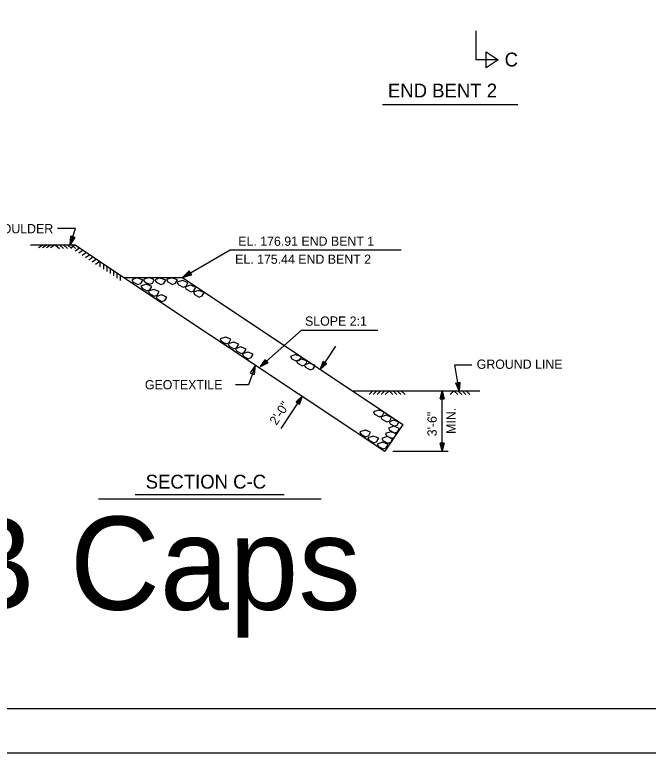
# Model space of a CAD drawing. Extents: x -102 to 265, y 0 to 198.
# Drawn here: x 115.3 to 183.9, y 0 to 80 of the extents above; entities that cross this region are included whole.
import ezdxf

# ---------------------------------------------------------------- set-up
doc = ezdxf.new("R2010")
doc.units = 0
for name, color, linetype in [('Arrowhead Terminators', 7, 'Continuous'), ('Arrowhead Terminators CELL', 7, 'Continuous'), ('Dimension Lines', 7, 'Continuous'), ('Mis Center Lines', 7, 'Continuous'), ('Mis Object Lines', 7, 'Continuous'), ('Miscellaneous Lines', 7, 'Continuous'), ('Plan Sheet', 7, 'Continuous'), ('Plot Shape', 7, 'Continuous'), ('Subtitle Text', 7, 'Continuous'), ('Text', 7, 'Continuous'), ('User Information Notes', 7, 'Continuous')]:
    doc.layers.add(name, color=color, linetype=linetype)

msp = doc.modelspace()

# ---------------------------------------------------------------- linework, layer by layer
at = {"layer": 'Arrowhead Terminators'}
msp.add_lwpolyline([(141.383, 42.059), (140.809, 41.203), (141.279, 41.033)], close=True, dxfattribs=at)
at = {"layer": 'Arrowhead Terminators CELL'}
msp.add_lwpolyline([(167.667, 75.143), (166.377, 74.283), (166.377, 76.002)], close=True, dxfattribs=at)
at = {"layer": 'Dimension Lines'}
for p, q in [((167.667, 75.143), (165.264, 75.143)), ((133.46, 51.561), (138.645, 54.554)), ((138.645, 54.554), (157.172, 54.554)), ((150.054, 44.094), (148.387, 41.594)), ((161.607, 32.712), (161.607, 39.276)), ((146.451, 38.69), (144.123, 35.198)), ((156.255, 32.712), (162.249, 32.712)), ((128.355, 28.052), (144.488, 28.052)), ((124.365, 27.552), (148.478, 27.552))]:
    msp.add_line(p, q, dxfattribs=at)
for points in [[(165.264, 75.143), (165.264, 78.288)], [(121.324, 55.129), (121.875, 56.857), (119.947, 56.857)], [(121.59, 55.965), (121.632, 55.952), (121.324, 55.129), (121.674, 55.939), (121.716, 55.925), (121.324, 55.129), (121.757, 55.911), (121.8, 55.898), (121.324, 55.129), (121.381, 56.031), (121.424, 56.018), (121.324, 55.129), (121.465, 56.005), (121.506, 55.992), (121.324, 55.129), (121.549, 55.978), (121.8, 55.898), (121.381, 56.031), (121.324, 55.129), (121.8, 55.898)], [(134.324, 52.06), (134.349, 52.017), (133.46, 51.561), (134.374, 51.974), (134.399, 51.93), (133.46, 51.561), (134.424, 51.887), (134.449, 51.844), (133.46, 51.561), (134.2, 52.276), (134.224, 52.233), (133.46, 51.561), (134.249, 52.189), (134.274, 52.147), (133.46, 51.561), (134.299, 52.103), (134.449, 51.844), (134.2, 52.276), (133.46, 51.561), (134.449, 51.844)], [(141.916, 41.895), (146.364, 45.837), (154.625, 45.837)], [(142.574, 42.478), (142.603, 42.446), (141.916, 41.895), (142.631, 42.412), (142.661, 42.379), (141.916, 41.895), (142.69, 42.347), (142.719, 42.313), (141.916, 41.895), (142.428, 42.642), (142.457, 42.609), (141.916, 41.895), (142.486, 42.576), (142.515, 42.543), (141.916, 41.895), (142.544, 42.511), (142.719, 42.313), (142.428, 42.642), (141.916, 41.895), (142.719, 42.313)], [(148.874, 42.325), (148.911, 42.301), (148.387, 41.594), (148.948, 42.277), (148.984, 42.252), (148.387, 41.594), (149.02, 42.228), (149.057, 42.203), (148.387, 41.594), (148.692, 42.447), (148.728, 42.423), (148.387, 41.594), (148.765, 42.399), (148.802, 42.374), (148.387, 41.594), (148.838, 42.35), (149.057, 42.203), (148.692, 42.447), (148.387, 41.594), (149.057, 42.203)], [(141.383, 42.059), (140.616, 39.93), (139.212, 39.93)], [(163.418, 39.277), (162.959, 42.076), (164.794, 42.076)], [(163.275, 40.144), (163.319, 40.151), (163.418, 39.277), (163.362, 40.157), (163.406, 40.165), (163.418, 39.277), (163.449, 40.172), (163.492, 40.179), (163.418, 39.277), (163.059, 40.108), (163.103, 40.116), (163.418, 39.277), (163.146, 40.122), (163.189, 40.13), (163.418, 39.277), (163.232, 40.136), (163.492, 40.179), (163.059, 40.108), (163.418, 39.277), (163.492, 40.179)], [(161.607, 38.399), (161.563, 38.399), (161.607, 39.276), (161.519, 38.399), (161.475, 38.399), (161.607, 39.276), (161.431, 38.399), (161.388, 38.399), (161.607, 39.276), (161.826, 38.399), (161.782, 38.399), (161.607, 39.276), (161.738, 38.399), (161.695, 38.399), (161.607, 39.276), (161.65, 38.399), (161.388, 38.399), (161.826, 38.399), (161.607, 39.276), (161.388, 38.399)], [(145.964, 37.96), (145.927, 37.984), (146.451, 38.69), (145.891, 38.009), (145.854, 38.033), (146.451, 38.69), (145.818, 38.057), (145.782, 38.081), (146.451, 38.69), (146.147, 37.838), (146.11, 37.862), (146.451, 38.69), (146.073, 37.887), (146.037, 37.911), (146.451, 38.69), (146.001, 37.935), (145.782, 38.081), (146.147, 37.838), (146.451, 38.69), (145.782, 38.081)], [(161.607, 33.59), (161.65, 33.59), (161.607, 32.712), (161.695, 33.59), (161.738, 33.59), (161.607, 32.712), (161.782, 33.59), (161.826, 33.59), (161.607, 32.712), (161.388, 33.59), (161.431, 33.59), (161.607, 32.712), (161.475, 33.59), (161.519, 33.59), (161.607, 32.712), (161.563, 33.59), (161.826, 33.59), (161.388, 33.59), (161.607, 32.712), (161.826, 33.59)]]:
    msp.add_lwpolyline(points, dxfattribs=at)
at = {"layer": 'Mis Center Lines'}
for points in [[(128.564, 51.499), (128.002, 51.298), (128.122, 51.056), (128.645, 50.776), (128.966, 50.897), (129.167, 51.257), (128.685, 51.459), (128.685, 51.499), (128.564, 51.459)], [(129.816, 51.536), (129.254, 51.336), (129.374, 51.094), (129.896, 50.813), (130.217, 50.934), (130.418, 51.295), (129.937, 51.496), (129.937, 51.536), (129.816, 51.496)], [(131.061, 51.496), (130.499, 51.295), (130.62, 51.054), (131.142, 50.773), (131.463, 50.893), (131.664, 51.255), (131.182, 51.456), (131.182, 51.496), (131.061, 51.456)], [(132.316, 51.521), (131.753, 51.32), (131.874, 51.079), (132.396, 50.799), (132.717, 50.919), (132.918, 51.28), (132.436, 51.481), (132.436, 51.521), (132.316, 51.481)], [(133.46, 51.226), (132.897, 51.025), (133.018, 50.785), (133.541, 50.504), (133.862, 50.624), (134.062, 50.986), (133.581, 51.187), (133.581, 51.226), (133.46, 51.187)], [(129.537, 50.819), (128.975, 50.619), (129.095, 50.378), (129.617, 50.097), (129.938, 50.217), (130.139, 50.579), (129.657, 50.78), (129.657, 50.819), (129.537, 50.78)], [(134.318, 50.714), (133.756, 50.513), (133.876, 50.272), (134.398, 49.991), (134.719, 50.112), (134.92, 50.473), (134.438, 50.674), (134.438, 50.714), (134.318, 50.674)], [(130.329, 50.253), (129.767, 50.052), (129.887, 49.812), (130.409, 49.53), (130.73, 49.651), (130.932, 50.013), (130.45, 50.213), (130.45, 50.253), (130.329, 50.213)], [(131.167, 49.668), (130.605, 49.467), (130.725, 49.226), (131.247, 48.945), (131.569, 49.066), (131.77, 49.427), (131.288, 49.628), (131.288, 49.668), (131.167, 49.628)], [(135.211, 50.156), (134.648, 49.956), (134.769, 49.715), (135.291, 49.434), (135.612, 49.555), (135.813, 49.915), (135.331, 50.116), (135.331, 50.156), (135.211, 50.116)], [(138.117, 45.095), (137.555, 44.894), (137.676, 44.653), (138.198, 44.372), (138.519, 44.492), (138.72, 44.854), (138.238, 45.055), (138.238, 45.095), (138.117, 45.055)], [(138.97, 44.554), (138.408, 44.353), (138.528, 44.112), (139.05, 43.83), (139.371, 43.951), (139.572, 44.313), (139.09, 44.513), (139.09, 44.554), (138.97, 44.513)], [(139.76, 44.031), (139.197, 43.83), (139.318, 43.59), (139.84, 43.309), (140.162, 43.429), (140.362, 43.791), (139.88, 43.991), (139.88, 44.031), (139.76, 43.991)], [(140.523, 43.464), (139.961, 43.264), (140.081, 43.023), (140.603, 42.742), (140.924, 42.862), (141.125, 43.224), (140.644, 43.425), (140.644, 43.464), (140.523, 43.425)], [(145.743, 43.188), (145.181, 42.988), (145.301, 42.747), (145.823, 42.466), (146.145, 42.586), (146.346, 42.948), (145.864, 43.149), (145.864, 43.188), (145.743, 43.149)], [(146.386, 42.706), (145.823, 42.506), (145.944, 42.265), (146.466, 41.983), (146.787, 42.104), (146.988, 42.466), (146.506, 42.666), (146.506, 42.706), (146.386, 42.666)], [(147.229, 42.265), (146.667, 42.064), (146.787, 41.823), (147.309, 41.542), (147.631, 41.663), (147.832, 42.025), (147.349, 42.225), (147.349, 42.265), (147.229, 42.225)], [(154.721, 37.18), (154.159, 36.979), (154.28, 36.738), (154.801, 36.457), (155.122, 36.578), (155.323, 36.939), (154.842, 37.14), (154.842, 37.18), (154.721, 37.14)], [(155.51, 36.625), (154.948, 36.424), (155.069, 36.183), (155.591, 35.902), (155.912, 36.023), (156.112, 36.384), (155.631, 36.585), (155.631, 36.625), (155.51, 36.585)], [(156.361, 36.102), (155.855, 35.922), (155.963, 35.705), (156.433, 35.452), (156.722, 35.561), (156.904, 35.886), (156.469, 36.066), (156.469, 36.102), (156.361, 36.066)], [(156.344, 35.438), (155.783, 35.238), (155.903, 34.996), (156.425, 34.715), (156.746, 34.836), (156.947, 35.198), (156.465, 35.398), (156.465, 35.438), (156.344, 35.398)], [(153.245, 35.02), (152.682, 34.819), (152.803, 34.578), (153.325, 34.297), (153.646, 34.417), (153.847, 34.779), (153.365, 34.979), (153.365, 35.02), (153.245, 34.979)], [(156.023, 34.836), (155.461, 34.635), (155.582, 34.394), (156.104, 34.113), (156.425, 34.233), (156.626, 34.595), (156.144, 34.795), (156.144, 34.836), (156.023, 34.795)], [(154.12, 34.362), (153.557, 34.161), (153.677, 33.92), (154.199, 33.64), (154.521, 33.76), (154.722, 34.121), (154.24, 34.322), (154.24, 34.362), (154.12, 34.322)], [(155.132, 33.691), (154.57, 33.491), (154.69, 33.25), (155.212, 32.969), (155.534, 33.089), (155.734, 33.451), (155.252, 33.652), (155.252, 33.691), (155.132, 33.652)], [(155.622, 34.314), (155.06, 34.113), (155.181, 33.872), (155.702, 33.591), (156.023, 33.711), (156.224, 34.072), (155.742, 34.274), (155.742, 34.314), (155.622, 34.274)]]:
    msp.add_lwpolyline(points, dxfattribs=at)
at = {"layer": 'Mis Object Lines'}
for p, q in [((118.383, 55.072), (117.873, 54.779)), ((118.822, 55.072), (118.312, 54.779)), ((119.26, 55.072), (118.752, 54.779)), ((119.7, 55.072), (119.19, 54.779)), ((119.7, 55.072), (120.148, 54.696)), ((120.138, 55.072), (120.587, 54.696)), ((120.578, 55.072), (121.026, 54.696)), ((121.016, 55.072), (121.465, 54.696)), ((121.86, 55.072), (121.379, 54.737)), ((121.455, 55.072), (121.904, 54.696)), ((122.346, 54.748), (121.867, 54.412)), ((122.711, 54.505), (122.232, 54.169)), ((123.076, 54.261), (122.598, 53.926)), ((123.442, 54.018), (122.963, 53.682)), ((123.807, 53.774), (123.327, 53.438)), ((124.172, 53.531), (123.693, 53.195)), ((124.537, 53.287), (124.058, 52.951)), ((124.537, 53.287), (124.537, 52.702)), ((124.902, 53.043), (124.902, 52.458)), ((125.268, 52.8), (125.268, 52.215)), ((125.633, 52.556), (125.633, 51.971)), ((125.999, 52.312), (125.999, 51.727)), ((126.364, 52.07), (126.364, 51.484)), ((126.729, 51.826), (126.729, 51.24)), ((151.888, 39.276), (159.191, 39.276)), ((154.086, 39.276), (153.672, 38.862)), ((154.525, 39.276), (154.111, 38.862)), ((154.963, 39.276), (154.55, 38.862)), ((155.403, 39.276), (154.988, 38.862)), ((155.842, 39.276), (155.428, 38.862)), ((155.842, 39.276), (156.256, 38.862)), ((156.281, 39.276), (156.694, 38.862)), ((156.72, 39.276), (157.134, 38.862)), ((157.159, 39.276), (157.572, 38.862)), ((159.191, 39.276), (165.666, 39.276)), ((162.865, 39.276), (162.451, 38.862)), ((162.865, 39.276), (163.279, 38.862)), ((163.304, 39.276), (163.718, 38.862)), ((163.743, 39.276), (164.157, 38.862)), ((164.182, 39.276), (164.596, 38.862))]:
    msp.add_line(p, q, dxfattribs=at)
at = {"layer": 'Miscellaneous Lines'}
for p, q in [((117.031, 55.075), (121.86, 55.075)), ((121.86, 55.075), (127.13, 51.561)), ((127.13, 51.561), (133.46, 51.561)), ((127.13, 51.561), (155.403, 32.712)), ((133.46, 51.561), (157.351, 35.635)), ((157.351, 35.635), (155.403, 32.712))]:
    msp.add_line(p, q, dxfattribs=at)
at = {"layer": 'Plan Sheet'}
msp.add_line((8.432, 4.849), (264.435, 4.849), dxfattribs=at)
at = {"layer": 'Plot Shape'}
msp.add_lwpolyline([(0, 176), (264.505, 176), (264.505, 0), (0, 0)], close=True, dxfattribs=at)
at = {"layer": 'Subtitle Text'}
msp.add_line((155.144, 70.301), (169.774, 70.301), dxfattribs=at)

# ---------------------------------------------------------------- texts
for s, p in [('C', (168.361, 74.413)), ('END BENT 2', (155.721, 71.052))]:
    msp.add_text(s, height=1.5, dxfattribs=at).set_placement(p)
at = {"layer": 'Text'}
for s, height, p in [('SHOULDER', 1, (112.044, 56.34)), ('EL. 176.91 END BENT 1', 1, (139.514, 54.979)), ('EL. 175.44 END BENT 2', 1, (139.175, 53.031)), ('SLOPE 2:1', 1, (146.748, 46.322)), ('GROUND LINE', 1, (165.338, 41.654)), ('GEOTEXTILE', 1, (129.402, 39.43)), ('SECTION C-C', 1.5, (129.487, 28.674))]:
    msp.add_text(s, height=height, dxfattribs=at).set_placement(p)
for s, rotation, p in [('2\'-0"', 56.31045, (143.65, 35.471)), ('3\'-6"', 90, (161.004, 34.34)), ('MIN.', 90, (163.058, 34.604))]:
    msp.add_text(s, height=1, rotation=rotation, dxfattribs=at).set_placement(p)
at = {"layer": 'User Information Notes'}
msp.add_text('4\'-0" deep EB Caps', height=10.09146, dxfattribs=at).set_placement((35.135, 15.549))

doc.saveas('drawing.dxf')
